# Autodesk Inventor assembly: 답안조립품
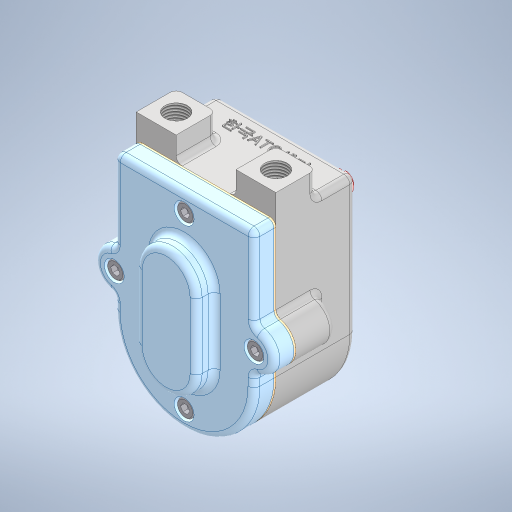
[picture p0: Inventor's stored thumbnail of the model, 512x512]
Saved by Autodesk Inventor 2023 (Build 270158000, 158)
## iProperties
Created: 2024-03
Part Number: 답안조립품
Document SubType Name: Assembly
Designer: asung
Author: asung
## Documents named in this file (9)
- C:\Users\asung\Desktop\740304V1006\답안조립품.iam
- C:\Users\asung\Desktop\740304V1006\본체.ipt
- C:\Users\asung\Desktop\740304V1006\오일레스 부시.ipt
- C:\Users\asung\Desktop\740304V1006\구동기어.ipt
- C:\Users\asung\Desktop\740304V1006\스퍼기어.ipt
- C:\Users\asung\Desktop\740304V1006\오일 실 14 25 7.ipt
- C:\Users\asung\Desktop\740304V1006\가스켓.ipt
- C:\Users\asung\Desktop\740304V1006\커버.ipt
- C:\Users\asung\Desktop\740304V1006\육각 소켓 머리 볼트 M5x12.ipt
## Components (2 placed, 2 different names)
1. 구동기어:1
2. 가스켓:1
